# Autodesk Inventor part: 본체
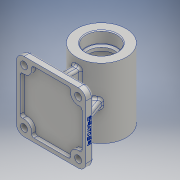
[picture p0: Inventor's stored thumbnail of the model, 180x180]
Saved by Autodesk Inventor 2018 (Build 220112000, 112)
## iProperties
Created: 2019-06
Part Number: 본체
Material: 알루미늄 6061
Document SubType Name: Modeling
Designer: Administrator
Density: 2.7 g/cm^3
Appearance: 알루미늄 - 평지
Author: Administrator
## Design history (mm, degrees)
sketch "스케치1" dims "d0" = 64
  geometry: L1 (0, -65)-(-45, -65); L2 (0, -65)-(45, -65); L3 (45, -65)-(45, -55); L4 (45, -55)-(-45, -55); L5 (-45, -55)-(-45, -65); 3 further points
  constraints: 10 end point, 2 perpendicular, 1 coincident, 1 horizontal, 1 vertical alignment, 2 other
  dimensions: "d2" = 45 distance of L1.start L1.end; "d3" = 45 distance of L1.start L2.end; "d4" = 10 distance of L2.end L3.end; "d5" = 90 distance of L3.end L4.end; "d80" = 65 distance from line of point (0, 0) L2
extrude "돌출1" new body sketch "스케치1" stored distance "d6" = 90; taper "d7" = 0 deg
sketch "스케치2"
  geometry: L1 (0, 0)-(90, 0) reference; L2 (90, 90)-(0, 90) reference; L3 (40, 10)-(40, 80); L4 (50, 10)-(50, 80); L5 (40, 10)-(50, 10); L6 (40, 80)-(50, 80); 1 further point
  constraints: 8 end point
extrude "돌출2" join sketch "스케치2" stored distance "d12" = 90; taper "d13" = 0 deg
sketch "스케치3"
  geometry: L1 (-35, -55)-(-17.958, -8.179); L2 (-45, -55)-(45, -55) reference; L3 (-35, -55)-(-5, -55); L4 (-17.958, -8.179)-(-5, -22.26); L5 (-5, -55)-(-5, -31.607) reference; L6 (-5, -22.26)-(-5, -55); 2 further points
  constraints: 8 end point, 1 collinear, 1 point on line, 1 other
  dimensions: "d14" = 10 distance of L2.start L1.start
extrude "돌출3" join sketch "스케치3" stored distance "d16" = 10; taper "d17" = 0 deg
fillet "모깎기1" dims "d18" = 10
fillet "모깎기2" dims "d19" = 3
fillet "모깎기3" dims "d20" = 3
fillet "모깎기4" dims "d21" = 3
fillet "모깎기5" dims "d22" = 3
hole "구멍1" diameter "d25" = 34; stored, may be unused: countersink angle "d29" = 90 deg, drill point angle "d31" = 118 deg; dims "d23" = 10, "d24" = 10, "d26" = 6, "d27" = 4, "d28" = 2, "d30" = 8
hole "구멍2" diameter "d34" = 40; stored, may be unused: countersink angle "d38" = 90 deg, drill point angle "d40" = 118 deg; dims "d32" = 10, "d33" = 10, "d35" = 6, "d36" = 4, "d37" = 2, "d39" = 15
hole "구멍3" diameter "d43" = 40; stored, may be unused: countersink angle "d47" = 90 deg, drill point angle "d49" = 118 deg; dims "d41" = 10, "d42" = 10, "d44" = 6, "d45" = 4, "d46" = 2, "d48" = 15
sketch "스케치4"
  geometry: L1 (0, 0)-(25, 0); L2 (25, 0)-(25, 21); L3 (25, 0)-(25, -21); L4 (22, -24)-(0, -24); L5 (0, -24)-(0, 24); L6 (0, 24)-(22, 24); A1 r 3 centre (22, 21) between (25, 21) and (22, 24); A2 r 3 centre (22, -21) between (22, -24) and (25, -21); 2 further points
  constraints: 12 end point, 4 perpendicular, 4 point on circle, 4 point on line, 4 tangent, 2 centre point, 1 equal radius, 1 horizontal, 1 vertical
  dimensions: "d50" = 25 distance of L1.start L1.end; "d51" = 24 distance of L1.end point (25, 24); "d52" = 24 distance of L1.end point (25, -24); "d53" = 3 radius of A1
revolve "회전1" sketch "스케치4" stored, may be unused: angle "d54" = 90 deg
sketch "스케치5"
  geometry: A1 r 10 centre (0, 7) between (-10, 7) and (0, -3) reference; A2 r 10 centre (0, 77) between (0, 87) and (-10, 77) reference; A3 r 10 centre (70, 77) between (80, 77) and (70, 87) reference; A4 r 10 centre (70, 7) between (70, -3) and (80, 7) reference; 5 further points
  constraints: 4 coincident
hole "구멍4" sketch "스케치5" at (0, 7), (0, 77), (70, 77), (70, 7) diameter "d55" = 9; stored, may be unused: countersink angle "d59" = 90 deg, drill point angle "d61" = 0 deg; dims "d56" = 6, "d57" = 4, "d58" = 2, "d60" = 15
chamfer "모따기1" distance "d62" = 1; stored, may be unused: second distance "d63" = 2, angle "d64" = 45 deg
fillet "모깎기6" dims "d65" = 0.6
sketch "스케치6"
  geometry: L1 (57.155, -85)-(12.845, -85); L2 (75, -22.845)-(75, -67.155); L3 (-5, -22.845)-(-5, -67.155); L4 (57.155, -5)-(12.845, -5); A1 r 10 centre (0, -80) between (9.881, -81.538) and (-1.538, -70.119); A2 r 10 centre (70, -80) between (71.538, -70.119) and (60.119, -81.538); A3 r 10 centre (70, -10) between (60.119, -8.462) and (71.538, -19.881); A4 r 10 centre (0, -10) between (-1.538, -19.881) and (9.881, -8.462); A5 r 3 centre (72, -22.845) between (75, -22.845) and (71.538, -19.881); A6 r 3 centre (72, -67.155) between (71.538, -70.119) and (75, -67.155); A7 r 3 centre (57.155, -82) between (57.155, -85) and (60.119, -81.538); A8 r 3 centre (12.845, -82) between (9.881, -81.538) and (12.845, -85); A9 r 3 centre (-2, -67.155) between (-5, -67.155) and (-1.538, -70.119); A10 r 3 centre (-2, -22.845) between (-1.538, -19.881) and (-5, -22.845); A11 r 3 centre (12.845, -8) between (12.845, -5) and (9.881, -8.462); A12 r 3 centre (57.155, -8) between (60.119, -8.462) and (57.155, -5); 13 further points
  constraints: 32 point on circle, 16 tangent, 12 centre point, 8 end point, 8 point on line, 7 equal radius, 4 coincident
  dimensions: "d75" = 3 radius of A5 (derived)
extrude "돌출4" cut sketch "스케치6" distance "d76" = 5; taper "d77" = 0 deg
node "작업 평면1"
sketch "스케치7"
  geometry: C1 r 5 at (0, 0); 1 further point
  constraints: 1 centre point, 1 coincident
  dimensions: "d78" = 10 diameter of C1
extrude "돌출5" join sketch "스케치7" distance "d81" = 3; taper "d83" = 0 deg; dims "d82" = 1.5, "d84" = 0
hole "구멍5" diameter "d87" = 4.917; stored, may be unused: countersink angle "d91" = 90 deg, drill point angle "d93" = 0 deg; dims "d85" = 10, "d86" = 10, "d88" = 12, "d89" = 4, "d90" = 2, "d92" = 17.1
fillet "모깎기7" dims "d94" = 2
sketch "스케치12"
  geometry: L1 (-10, 7)-(-10, 0) reference; L2 (0, 0)-(70, 0) reference; 2 further points
  constraints: 1 other
  dimensions: "d95" = 45 distance from line of L1 point (35, 4); "d96" = 4 distance from line of L2 point (35, 4)
feature "엠보싱1" sketch "스케치12" dims "d0" = 64, "d2" = 45, "d3" = 45, "d4" = 10, "d5" = 90, "d80" = 65, "d97" = 0.5, "d98" = 0
node "솔리드1" dims "d0" = 64, "d2" = 45, "d3" = 45, "d4" = 10, "d5" = 90, "d80" = 65
mirror "미러1"
